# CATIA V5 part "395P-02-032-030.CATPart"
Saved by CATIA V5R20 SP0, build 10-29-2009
Part number: 395P-02-032-030
Source: Unknown
Property "ARTICLENO": "395P-02-032-030"
Property "BOMINFO": "395P-02-032-030"
Property "CODE": "395P-02-032-030"
Property "D": "32.000"
Property "D1": "24.000"
Property "L": "95.000"
Property "L1": "45.000"
Property "L2": "10.000"
Property "L3": "32.000"
Property "L4": "5.000"
Property "LINA": "395P-02-032-030"
Property "M": "30.000"
Property "MAXLOAD": "1500 Kg"
Property "MDW": "3000 Kg"
Property "NB": "395P-02-032-030"
Property "NBSYN": "$CODE."
Property "NN": "395P"
Property "NT": "VDI 3366 Lifting Pins"
Property "R": "6.000"
Property "R1": "10.000"
Property "SUPPLIER": "CF"
Property "SW": "41.000"
Bounding box of the stored display mesh (mm): x -20.5 to 20.5, y -45 to 50, z -23.671 to 23.671
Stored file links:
  C:\Users\Utente\Desktop\3D files 395P\395P-02-032-030.CATPart
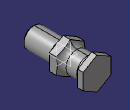
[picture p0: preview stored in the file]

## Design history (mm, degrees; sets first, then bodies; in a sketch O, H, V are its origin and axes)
Body1 "Geometry.1" (main body)
  Solid1 "395P-02-032-030.catpart": solid without history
